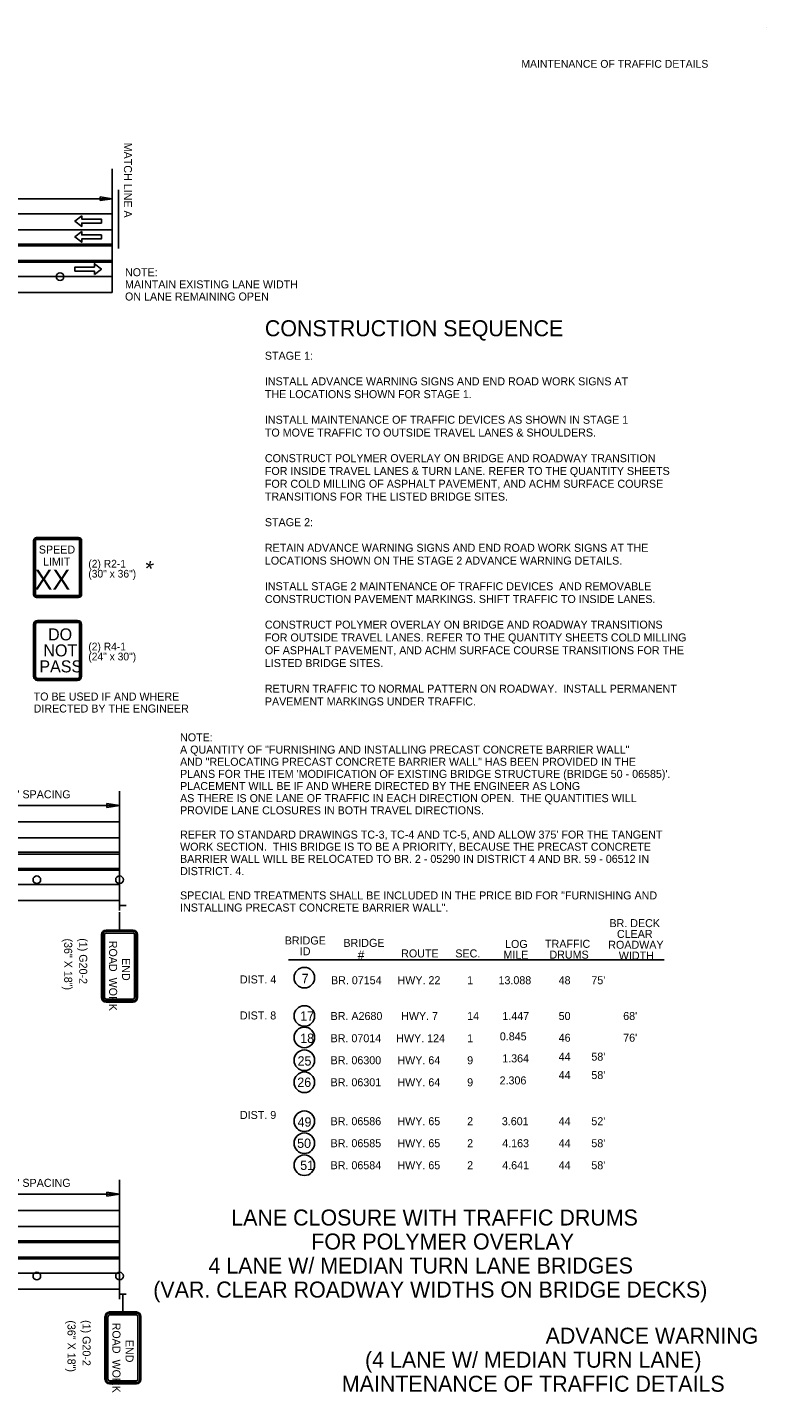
# Model space of a CAD drawing. Extents: x 1930579 to 1937984, y 596452 to 597630.
# Drawn here: x 1937430 to 1937984, y 596606 to 597630 of the extents above; entities that cross this region are included whole.
import ezdxf

# ---------------------------------------------------------------- set-up
doc = ezdxf.new("R2010")
doc.units = 0
for name, color, linetype in [('Default', 7, 'Continuous'), ('P_TC_Signs_Permanent', 7, 'Continuous'), ('P_TC_Signs_Temporary', 7, 'Continuous'), ('R_Border', 7, 'Continuous'), ('R_Striping', 7, 'Continuous'), ('S_AREA_CALC', 7, 'Continuous')]:
    doc.layers.add(name, color=color, linetype=linetype)

msp = doc.modelspace()

# ---------------------------------------------------------------- linework, layer by layer
at = {"layer": 'Default'}
for p, q in [((1937493.2, 597523.9), (1937493.2, 597431.2)), ((1937497.9, 597508.2), (1937497.9, 597464.2)), ((1937493.2, 597501.4), (1937241.5, 597501.4)), ((1937484.3, 597500.1), (1937484.3, 597502.8)), ((1937484.3, 597502.8), (1937493.2, 597501.4)), ((1937493.2, 597501.4), (1937484.3, 597500.1)), ((1937493.2, 597490.2), (1936493.1, 597490.2)), ((1937493.2, 597478.2), (1936493.3, 597478.2)), ((1937493.2, 597466), (1936492.7, 597466)), ((1937493.2, 597467.4), (1936493.5, 597467.4)), ((1937493.2, 597455.2), (1936493.3, 597455.2)), ((1937493.2, 597453.9), (1936493.3, 597453.9)), ((1937493.2, 597443.2), (1936493.3, 597443.2)), ((1937493.2, 597431.2), (1936493.3, 597431.2)), ((1937498.7, 597057.2), (1937498.7, 596975.3)), ((1937498.7, 597046.5), (1937332.4, 597046.5)), ((1937489.1, 597045), (1937489.1, 597047.9)), ((1937489.1, 597047.9), (1937498.7, 597046.5)), ((1937498.7, 597046.5), (1937489.1, 597045)), ((1937498.7, 597034.3), (1936493.1, 597034.3)), ((1936493.1, 597022.3), (1937498.7, 597022.3)), ((1937498.7, 597011.5), (1936493.1, 597011.5)), ((1937498.7, 597010.1), (1936493.1, 597010.1)), ((1937498.7, 596999.3), (1936493.1, 596999.3)), ((1937498.7, 596998), (1936493.1, 596998)), ((1936493.1, 596987.3), (1937498.7, 596987.3)), ((1937498.7, 596975.3), (1936493.1, 596975.3)), ((1937498.6, 596975.3), (1937498.6, 596967.8)), ((1937498.7, 596971.6), (1937503.8, 596971.6)), ((1937498.7, 596765.9), (1937498.7, 596683.9)), ((1937498.7, 596755.1), (1937332.4, 596755.1)), ((1937489.1, 596753.6), (1937489.1, 596756.5)), ((1937489.1, 596756.5), (1937498.7, 596755.1)), ((1937498.7, 596755.1), (1937489.1, 596753.6)), ((1937498.7, 596742.9), (1936493.1, 596742.9)), ((1936493.1, 596730.9), (1937498.7, 596730.9)), ((1937498.7, 596720.1), (1936493.1, 596720.1)), ((1937498.7, 596718.8), (1936493.1, 596718.8)), ((1937498.7, 596708), (1936493.1, 596708)), ((1937498.7, 596706.7), (1936493.1, 596706.7)), ((1936493.1, 596695.9), (1937498.7, 596695.9)), ((1937498.7, 596683.9), (1936493.1, 596683.9)), ((1937498.6, 596683.9), (1937498.6, 596676.4)), ((1937498.7, 596680.2), (1937503.8, 596680.2))]:
    msp.add_line(p, q, dxfattribs=at)
for centre, radius in [((1937454.1, 597443), 2.87), ((1937436.7, 596990.8), 2.87), ((1937498.7, 596990.8), 2.87), ((1937637.3, 596917.4), 7.71), ((1937637.3, 596888.7), 7.71), ((1937637.3, 596872.6), 7.71), ((1937637.3, 596855.5), 7.71), ((1937637.3, 596839), 7.71), ((1937637.3, 596809.8), 7.71), ((1937637.3, 596793.3), 7.71), ((1937637.3, 596776.8), 7.71), ((1937436.7, 596693.7), 2.87), ((1937498.7, 596693.7), 2.87)]:
    msp.add_circle(centre, radius, dxfattribs=at)
at = {"layer": 'P_TC_Signs_Permanent'}
for p, q in [((1937434.3, 597245.2), (1937434.3, 597204.7)), ((1937434.8, 597245.2), (1937434.8, 597204.7)), ((1937435.8, 597245.2), (1937435.8, 597204.7)), ((1937468, 597247.4), (1937436.5, 597247.4)), ((1937468, 597246.9), (1937436.5, 597246.9)), ((1937468, 597245.9), (1937436.5, 597245.9)), ((1937468.8, 597204.7), (1937468.8, 597245.2)), ((1937469.7, 597204.7), (1937469.7, 597245.2)), ((1937470.3, 597204.7), (1937470.3, 597245.2)), ((1937436.5, 597203.9), (1937468, 597203.9)), ((1937436.5, 597203), (1937468, 597203)), ((1937436.5, 597202.4), (1937468, 597202.4)), ((1937434.3, 597182.3), (1937434.3, 597143.3)), ((1937434.9, 597182.3), (1937434.9, 597143.3)), ((1937435.8, 597182.3), (1937435.8, 597143.3)), ((1937467.3, 597185.3), (1937437.3, 597185.3)), ((1937467.3, 597184.7), (1937437.3, 597184.7)), ((1937467.3, 597183.8), (1937437.3, 597183.8)), ((1937468.8, 597143.3), (1937468.8, 597182.3)), ((1937469.7, 597143.3), (1937469.7, 597182.3)), ((1937470.3, 597143.3), (1937470.3, 597182.3)), ((1937437.3, 597141.8), (1937467.3, 597141.8)), ((1937437.3, 597140.9), (1937467.3, 597140.9)), ((1937437.3, 597140.3), (1937467.3, 597140.3))]:
    msp.add_line(p, q, dxfattribs=at)
for centre, radius, start, end in [((1937436.5, 597245.2), 2.25, 90.003, 180.003), ((1937436.5, 597245.2), 1.69, 90.003, 180.003), ((1937436.5, 597245.2), 0.75, 90.003, 180.003), ((1937468, 597245.2), 2.25, 0.003, 90.003), ((1937468, 597245.2), 1.69, 0.003, 90.003), ((1937468, 597245.2), 0.75, 0.003, 90.003), ((1937436.5, 597204.7), 2.25, 180.003, 270.003), ((1937436.5, 597204.7), 1.69, 180.003, 270.003), ((1937436.5, 597204.7), 0.75, 180.003, 270.003), ((1937468, 597204.7), 2.25, 270.003, 0.003), ((1937468, 597204.7), 1.69, 270.003, 0.003), ((1937468, 597204.7), 0.75, 270.003, 0.003), ((1937437.3, 597182.3), 3, 90.003, 180.003), ((1937437.3, 597182.3), 2.4, 90.003, 180.003), ((1937437.3, 597182.3), 1.5, 90.003, 180.003), ((1937467.3, 597182.3), 3, 0.003, 90.003), ((1937467.3, 597182.3), 2.4, 0.003, 90.003), ((1937467.3, 597182.3), 1.5, 0.003, 90.003), ((1937437.3, 597143.3), 3, 180.003, 270.003), ((1937437.3, 597143.3), 2.4, 180.003, 270.003), ((1937437.3, 597143.3), 1.5, 180.003, 270.003), ((1937467.3, 597143.3), 3, 270.003, 0.003), ((1937467.3, 597143.3), 2.4, 270.003, 0.003), ((1937467.3, 597143.3), 1.5, 270.003, 0.003)]:
    msp.add_arc(centre, radius, start, end, dxfattribs=at)
at = {"layer": 'P_TC_Signs_Temporary'}
for p, q in [((1937508.9, 596953.1), (1937488.6, 596953.1)), ((1937508.9, 596952.2), (1937488.6, 596952.2)), ((1937485.2, 596949.7), (1937485.2, 596902.5)), ((1937486.2, 596949.7), (1937486.2, 596902.5)), ((1937487.5, 596949.7), (1937487.5, 596902.5)), ((1937508.9, 596950.9), (1937488.6, 596950.9)), ((1937510, 596902.5), (1937510, 596949.7)), ((1937511.3, 596902.5), (1937511.3, 596949.7)), ((1937512.2, 596902.5), (1937512.2, 596949.7)), ((1937488.6, 596901.4), (1937508.9, 596901.4)), ((1937488.6, 596900), (1937508.9, 596900)), ((1937488.6, 596899.1), (1937508.9, 596899.1)), ((1937511.4, 596666.8), (1937491.2, 596666.8)), ((1937511.4, 596665.9), (1937491.2, 596665.9)), ((1937487.8, 596663.4), (1937487.8, 596616.2)), ((1937488.7, 596663.4), (1937488.7, 596616.2)), ((1937490, 596663.4), (1937490, 596616.2)), ((1937511.4, 596664.6), (1937491.2, 596664.6)), ((1937512.5, 596616.2), (1937512.5, 596663.4)), ((1937513.9, 596616.2), (1937513.9, 596663.4)), ((1937514.8, 596616.2), (1937514.8, 596663.4)), ((1937491.2, 596615.1), (1937511.4, 596615.1)), ((1937491.2, 596613.8), (1937511.4, 596613.8)), ((1937491.2, 596612.8), (1937511.4, 596612.8))]:
    msp.add_line(p, q, dxfattribs=at)
for centre, radius, start, end in [((1937488.6, 596949.7), 3.37, 90, 180), ((1937488.6, 596949.7), 2.44, 90, 180), ((1937508.9, 596949.7), 3.37, 360, 90), ((1937508.9, 596949.7), 2.44, 360, 90), ((1937488.6, 596949.7), 1.13, 90, 180), ((1937508.9, 596949.7), 1.13, 360, 90), ((1937488.6, 596902.5), 3.37, 180, 270), ((1937488.6, 596902.5), 2.44, 180, 270), ((1937488.6, 596902.5), 1.13, 180, 270), ((1937508.9, 596902.5), 2.44, 270, 360), ((1937508.9, 596902.5), 1.13, 270, 360), ((1937508.9, 596902.5), 3.38, 270, 360), ((1937491.2, 596663.4), 3.37, 90, 180), ((1937491.2, 596663.4), 2.44, 90, 180), ((1937511.4, 596663.4), 3.37, 360, 90), ((1937511.4, 596663.4), 2.44, 360, 90), ((1937491.2, 596663.4), 1.13, 90, 180), ((1937511.4, 596663.4), 1.13, 360, 90), ((1937491.2, 596616.2), 3.37, 180, 270), ((1937491.2, 596616.2), 2.44, 180, 270), ((1937491.2, 596616.2), 1.13, 180, 270), ((1937511.4, 596616.2), 2.44, 270, 360), ((1937511.4, 596616.2), 1.13, 270, 360), ((1937511.4, 596616.2), 3.38, 270, 360)]:
    msp.add_arc(centre, radius, start, end, dxfattribs=at)
at = {"layer": 'R_Border'}
for p, q in [((1937498.7, 596953.1), (1937498.7, 596966.5)), ((1937625.5, 596930.8), (1937907.2, 596930.8)), ((1937501.3, 596666.8), (1937501.3, 596680.2))]:
    msp.add_line(p, q, dxfattribs=at)
at = {"layer": 'R_Striping'}
for points in [[(1937470.4, 597488.6), (1937465.2, 597484.6), (1937470.4, 597480.6), (1937470.4, 597483.1), (1937485.1, 597483.1), (1937485.1, 597486.1), (1937470.4, 597486.1)], [(1937470.4, 597476.8), (1937465.2, 597472.8), (1937470.4, 597468.8), (1937470.4, 597471.3), (1937485.1, 597471.3), (1937485.1, 597474.3), (1937470.4, 597474.3)], [(1937479.9, 597444.6), (1937485.1, 597448.6), (1937479.9, 597452.6), (1937479.9, 597450.1), (1937465.2, 597450.1), (1937465.2, 597447.1), (1937479.9, 597447.1)]]:
    msp.add_lwpolyline(points, close=True, dxfattribs=at)
at = {"layer": 'S_AREA_CALC'}
msp.add_line((1937984, 597629.9), (1937984, 597629.9), dxfattribs=at)

# ---------------------------------------------------------------- texts
at = {"layer": 'Default'}
for s, rotation, p in [('MATCH LINE A', 270, (1937502, 597543.4)), ("TRAFFIC DRUMS @ 60' SPACING", 360, (1937335.1, 597051.9)), ("TRAFFIC DRUMS @ 60' SPACING", 360, (1937335.1, 596760.6))]:
    msp.add_text(s, height=6, rotation=rotation, dxfattribs=at).set_placement(p)
for s, p in [('LANE CLOSURE WITH TRAFFIC DRUMS', (1937582.5, 596731.6)), ('FOR POLYMER OVERLAY ', (1937642.5, 596713.6)), ('4 LANE W/ MEDIAN TURN LANE BRIDGES', (1937565.4, 596695.6)), ('(VAR. CLEAR ROADWAY WIDTHS ON BRIDGE DECKS)', (1937524, 596677.6))]:
    msp.add_text(s, height=12, dxfattribs=at).set_placement(p)
at = {"layer": 'P_TC_Signs_Permanent'}
for s, height, rotation, p in [('SPEED', 6, 0.003, (1937438.2, 597235.4)), ('LIMIT', 6, 0.003, (1937441.3, 597226.4)), ('XX', 15, 0.003, (1937435, 597208.4)), ('DO', 9, 0.003, (1937445.1, 597170.3)), ('NOT', 9, 359.9626, (1937441.6, 597158.3)), ('PASS', 9, 0.003, (1937438.6, 597146.3))]:
    msp.add_text(s, height=height, rotation=rotation, dxfattribs=at).set_placement(p)
at = {"layer": 'P_TC_Signs_Temporary'}
for s, p in [('ROAD  WORK', (1937490.9, 596945.1)), ('END', (1937500.6, 596932.1)), ('ROAD  WORK', (1937493.4, 596658.8)), ('END', (1937503.2, 596645.9))]:
    msp.add_text(s, height=6, rotation=270, dxfattribs=at).set_placement(p)
at = {"layer": 'R_Border'}
for s, height, rotation, p in [('NOTE:', 6, 360, (1937502.8, 597443.3)), ('MAINTAIN EXISTING LANE WIDTH', 6, 360, (1937502.8, 597434.2)), ('ON LANE REMAINING OPEN', 6, 360, (1937502.8, 597425.1)), ('CONSTRUCTION SEQUENCE', 12, 360, (1937607.7, 597398.3)), ('STAGE 1:', 6, 360, (1937607.7, 597380.7)), ('INSTALL ADVANCE WARNING SIGNS AND END ROAD WORK SIGNS AT', 6, 360, (1937607.7, 597361.5)), ('THE LOCATIONS SHOWN FOR STAGE 1.', 6, 360, (1937607.7, 597351.9)), ('INSTALL MAINTENANCE OF TRAFFIC DEVICES AS SHOWN IN STAGE 1', 6, 360, (1937607.7, 597332.7)), ('TO MOVE TRAFFIC TO OUTSIDE TRAVEL LANES & SHOULDERS.', 6, 360, (1937607.7, 597323.1)), ('CONSTRUCT POLYMER OVERLAY ON BRIDGE AND ROADWAY TRANSITION', 6, 360, (1937607.7, 597303.9)), ('FOR INSIDE TRAVEL LANES & TURN LANE. REFER TO THE QUANTITY SHEETS ', 6, 360, (1937607.7, 597294.3)), ('FOR COLD MILLING OF ASPHALT PAVEMENT, AND ACHM SURFACE COURSE ', 6, 360, (1937607.7, 597284.7)), ('TRANSITIONS FOR THE LISTED BRIDGE SITES.', 6, 360, (1937607.7, 597275.1)), ('STAGE 2:', 6, 360, (1937607.7, 597255.9)), ('RETAIN ADVANCE WARNING SIGNS AND END ROAD WORK SIGNS AT THE', 6, 360, (1937607.7, 597236.7)), ('(2) R2-1', 5.76, 0.003, (1937475.3, 597224.9)), ('*', 12, 135.003, (1937529.7, 597230.8)), ('LOCATIONS SHOWN ON THE STAGE 2 ADVANCE WARNING DETAILS.', 6, 360, (1937607.7, 597227.1)), ('(30" x 36")', 5.76, 0.003, (1937475.3, 597217.4)), ('INSTALL STAGE 2 MAINTENANCE OF TRAFFIC DEVICES  AND REMOVABLE', 6, 360, (1937607.7, 597207.9)), ('CONSTRUCTION PAVEMENT MARKINGS. SHIFT TRAFFIC TO INSIDE LANES.', 6, 360, (1937607.7, 597198.3)), ('CONSTRUCT POLYMER OVERLAY ON BRIDGE AND ROADWAY TRANSITIONS', 6, 360, (1937607.7, 597179.1)), ('(2) R4-1', 5.76, 0.003, (1937475.3, 597162.8)), ('FOR OUTSIDE TRAVEL LANES. REFER TO THE QUANTITY SHEETS COLD MILLING ', 6, 360, (1937607.7, 597169.5)), ('(24" x 30")', 5.76, 0.003, (1937475.3, 597155.3)), ('OF ASPHALT PAVEMENT, AND ACHM SURFACE COURSE TRANSITIONS FOR THE ', 6, 360, (1937607.7, 597159.9)), ('LISTED BRIDGE SITES.', 6, 360, (1937607.7, 597150.3)), ('RETURN TRAFFIC TO NORMAL PATTERN ON ROADWAY.  INSTALL PERMANENT', 6, 360, (1937607.7, 597131.1)), ('TO BE USED IF AND WHERE', 6, 360, (1937434.3, 597125.2)), ('PAVEMENT MARKINGS UNDER TRAFFIC.', 6, 360, (1937607.7, 597121.5)), ('DIRECTED BY THE ENGINEER', 6, 360, (1937434.3, 597116.2)), ('NOTE:', 6, 360, (1937544.1, 597094.6)), ('A QUANTITY OF "FURNISHING AND INSTALLING PRECAST CONCRETE BARRIER WALL" ', 6, 360, (1937544.1, 597085.4)), ('AND "RELOCATING PRECAST CONCRETE BARRIER WALL" HAS BEEN PROVIDED IN THE ', 6, 360, (1937544.1, 597076.3)), ("PLANS FOR THE ITEM 'MODIFICATION OF EXISTING BRIDGE STRUCTURE (BRIDGE 50 - 06585)'. ", 6, 360, (1937544.1, 597067.2)), ('AS THERE IS ONE LANE OF TRAFFIC IN EACH DIRECTION OPEN.  THE QUANTITIES WILL', 6, 360, (1937544.1, 597049)), ('PLACEMENT WILL BE IF AND WHERE DIRECTED BY THE ENGINEER AS LONG ', 6, 360, (1937544.1, 597058.1)), ('PROVIDE LANE CLOSURES IN BOTH TRAVEL DIRECTIONS.', 6, 360, (1937544.1, 597039.9)), ("REFER TO STANDARD DRAWINGS TC-3, TC-4 AND TC-5, AND ALLOW 375' FOR THE TANGENT", 6, 360, (1937544.1, 597021.7)), ('WORK SECTION.  THIS BRIDGE IS TO BE A PRIORITY, BECAUSE THE PRECAST CONCRETE ', 6, 360, (1937544.1, 597012.6)), ('BARRIER WALL WILL BE RELOCATED TO BR. 2 - 05290 IN DISTRICT 4 AND BR. 59 - 06512 IN ', 6, 360, (1937544.1, 597003.5)), ('DISTRICT. 4.', 6, 360, (1937544.1, 596994.3)), ('SPECIAL END TREATMENTS SHALL BE INCLUDED IN THE PRICE BID FOR "FURNISHING AND', 6, 360, (1937544.1, 596976.1)), ('INSTALLING PRECAST CONCRETE BARRIER WALL".', 6, 360, (1937544.1, 596967)), ('BR. DECK ', 6, 360, (1937866.1, 596955.3)), ('CLEAR', 6, 360, (1937871.7, 596947.2)), ('(36" X 18")', 6, 270, (1937457.2, 596946.8)), ('(1) G20-2', 6, 270, (1937468.5, 596947)), ('BRIDGE ', 6, 360, (1937622.6, 596942.3)), ('BRIDGE ', 6, 360, (1937666.6, 596940.5)), ('LOG', 6, 360, (1937787.8, 596939.7)), ('TRAFFIC ', 6, 360, (1937817.8, 596939.8)), ('ROADWAY ', 6, 360, (1937865.2, 596939.1)), ('ID', 6, 360, (1937633.9, 596934.2)), ('#', 6.71, 360, (1937677.3, 596931.1)), ('ROUTE', 6, 360, (1937709.9, 596932.6)), ('SEC.', 6, 360, (1937750.5, 596932.6)), ('MILE', 6, 360, (1937786.6, 596931.6)), ('DRUMS', 6, 360, (1937821.1, 596931.7)), ('WIDTH', 6, 360, (1937873.1, 596931)), ('DIST. 4', 6, 360, (1937589, 596913.1)), ('7', 7, 360, (1937635.3, 596913.3)), ('BR. 07154', 6, 360, (1937657.3, 596912.5)), ('HWY. 22', 6, 360, (1937707.2, 596912.5)), ('1', 6, 360, (1937759.4, 596912.5)), ('13.088', 6, 360, (1937782.9, 596912.5)), ("48       75'", 6, 360, (1937828, 596912.5)), ('DIST. 8', 6, 360, (1937589, 596886.1)), ('17', 7, 360, (1937634.2, 596885.2)), ('BR. A2680', 6, 360, (1937657, 596885.7)), ('HWY. 7', 6, 360, (1937709.9, 596885.7)), ('14', 6, 360, (1937759.4, 596885.7)), ('1.447', 6, 360, (1937785.8, 596885.7)), ('50', 6, 360, (1937828, 596885.7)), ("68'", 6, 360, (1937876.4, 596885.7)), ('18', 7, 360, (1937634.2, 596868.5)), ('BR. 07014', 6, 360, (1937657, 596869)), ('HWY. 124', 6, 360, (1937706.2, 596869)), ('1', 6, 360, (1937759.4, 596869)), ('0.845', 6, 360, (1937783.9, 596870.4)), ('46', 6, 360, (1937828, 596869.4)), ("76'", 6, 360, (1937876.4, 596869.4)), ('1.364', 6, 360, (1937785.7, 596853.9)), ("44       58'", 6, 360, (1937828, 596855.2)), ('25', 7, 360, (1937632.2, 596851.5)), ('BR. 06300', 6, 360, (1937657, 596852.5)), ('HWY. 64', 6, 360, (1937707.1, 596852.5)), ('9', 6, 360, (1937759.4, 596852.5)), ('26', 7, 360, (1937632, 596835.5)), ('BR. 06301', 6, 360, (1937657, 596836)), ('HWY. 64', 6, 360, (1937707.1, 596836)), ('9', 6, 360, (1937759.4, 596836)), ('2.306', 6, 360, (1937783.7, 596837.4)), ("44       58'", 6, 360, (1937828, 596841.4)), ('DIST. 9', 6, 360, (1937589, 596811.5)), ('49', 7, 360, (1937632.2, 596805.7)), ('BR. 06586', 6, 360, (1937657, 596806.8)), ('HWY. 65', 6, 360, (1937707.1, 596806.8)), ('2', 6, 360, (1937759.4, 596806.8)), ('3.601', 6, 360, (1937785.4, 596806.8)), ("44       52'", 6, 360, (1937828, 596806.8)), ('50', 7, 360, (1937631.9, 596789.8)), ('BR. 06585', 6, 360, (1937657, 596790.3)), ('HWY. 65', 6, 360, (1937707.1, 596790.3)), ('2', 6, 360, (1937759.4, 596790.3)), ('4.163', 6, 360, (1937785.7, 596790.3)), ("44       58'", 6, 360, (1937828, 596790.3)), ('51', 7, 360, (1937634.2, 596773.3)), ('BR. 06584', 6, 360, (1937657, 596773.8)), ('HWY. 65', 6, 360, (1937707.1, 596773.8)), ('2', 6, 360, (1937759.4, 596773.8)), ('4.641', 6, 360, (1937785.7, 596773.8)), ("44       58'", 6, 360, (1937828, 596773.8)), ('(36" X 18")', 6, 270, (1937459.7, 596660.5)), ('(1) G20-2', 6, 270, (1937471, 596660.7)), ('ADVANCE WARNING ', 12, 360, (1937818.2, 596643)), ('(4 LANE W/ MEDIAN TURN LANE)', 12, 360, (1937682.8, 596625)), ('MAINTENANCE OF TRAFFIC DETAILS', 12, 360, (1937665.4, 596607))]:
    msp.add_text(s, height=height, rotation=rotation, dxfattribs=at).set_placement(p)
at = {"layer": 'S_AREA_CALC'}
msp.add_text('MAINTENANCE OF TRAFFIC DETAILS', height=5.862, rotation=360, dxfattribs=at).set_placement((1937800, 597599.6))

doc.saveas('drawing.dxf')
